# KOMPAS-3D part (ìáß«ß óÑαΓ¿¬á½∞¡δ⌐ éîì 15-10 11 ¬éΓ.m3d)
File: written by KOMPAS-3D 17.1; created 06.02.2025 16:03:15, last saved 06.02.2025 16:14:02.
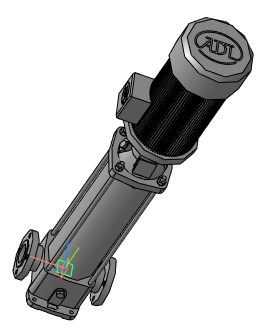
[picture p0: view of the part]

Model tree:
1. Операция без истории:1  (labels: Насос вертикальный ВМН 15-10 11 кВт)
